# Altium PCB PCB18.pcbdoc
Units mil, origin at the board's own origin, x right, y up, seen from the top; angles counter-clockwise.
Board outline 2150 x 1630 mil, 2 copper layers (Top Layer, Bottom Layer); 39 components, 29 nets, 133 pads, 20 vias.
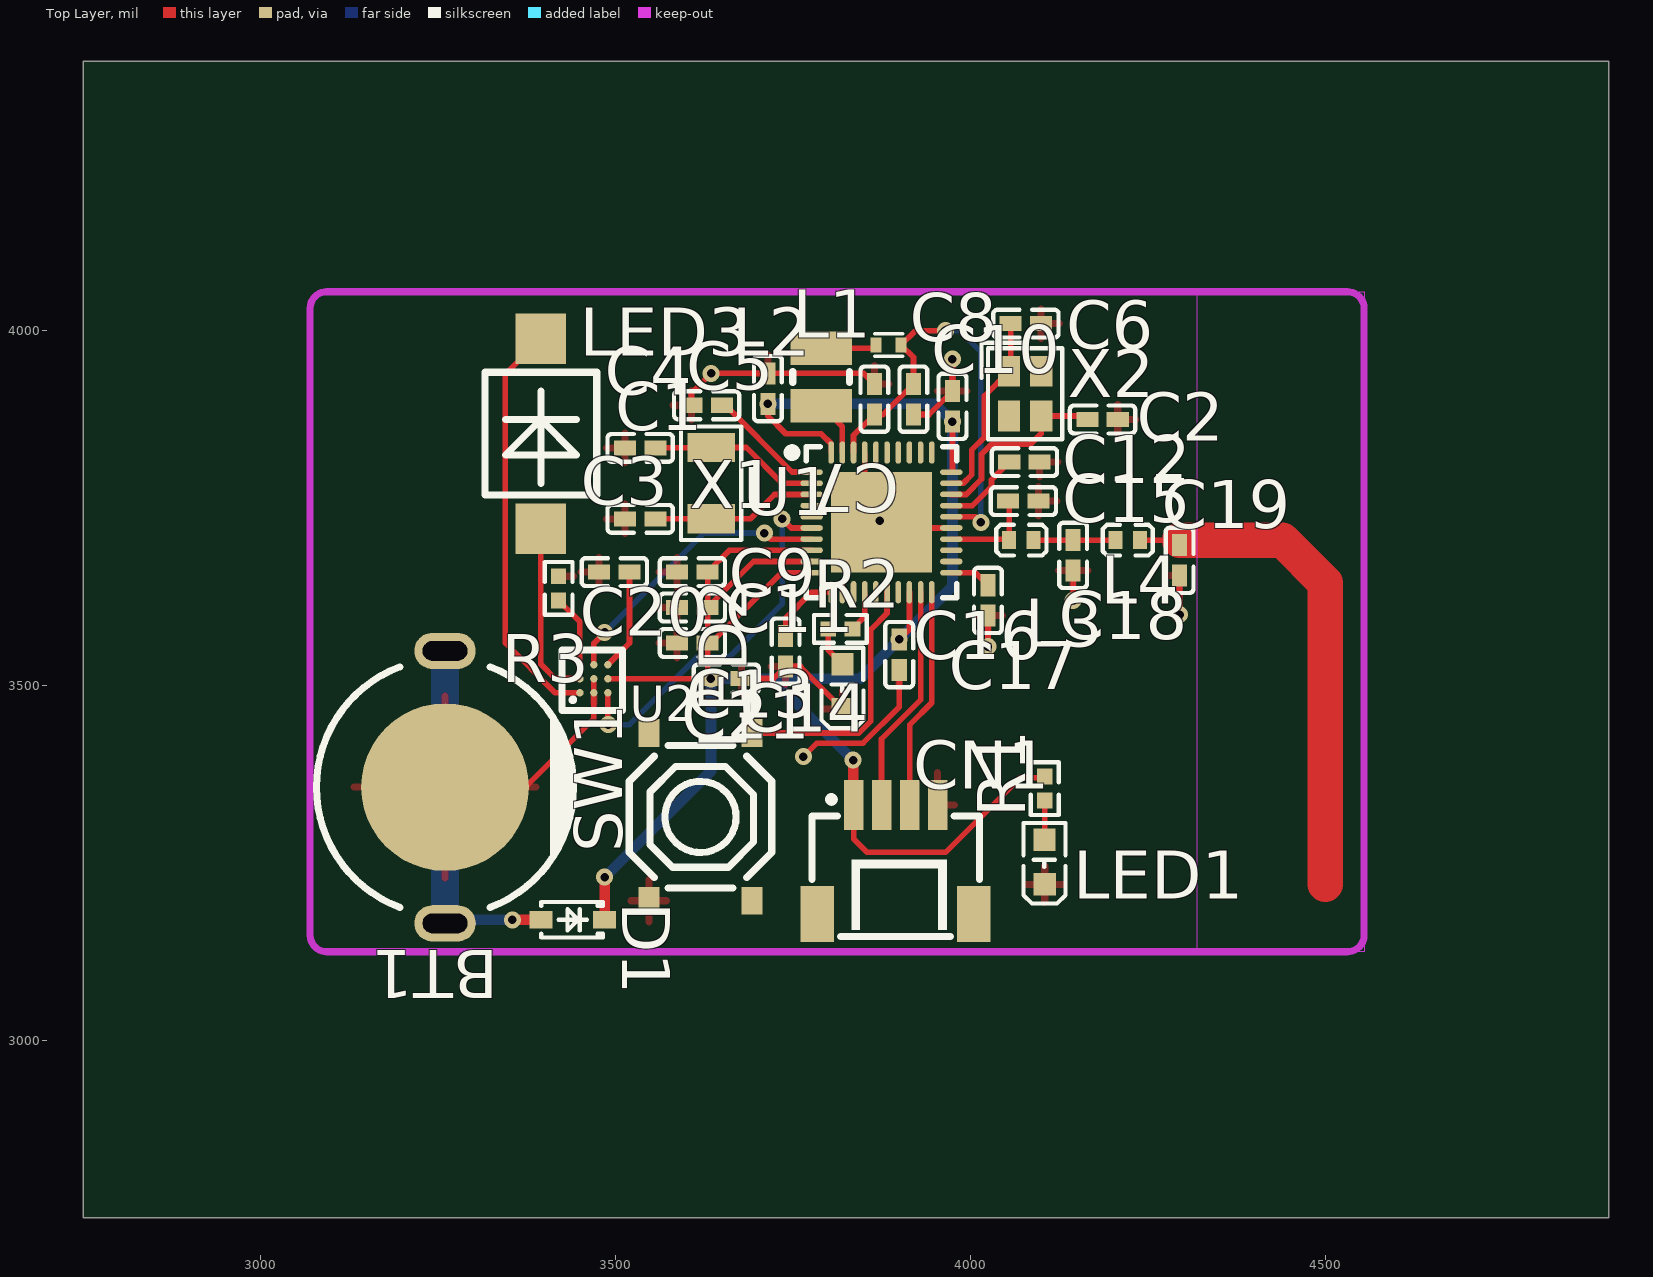
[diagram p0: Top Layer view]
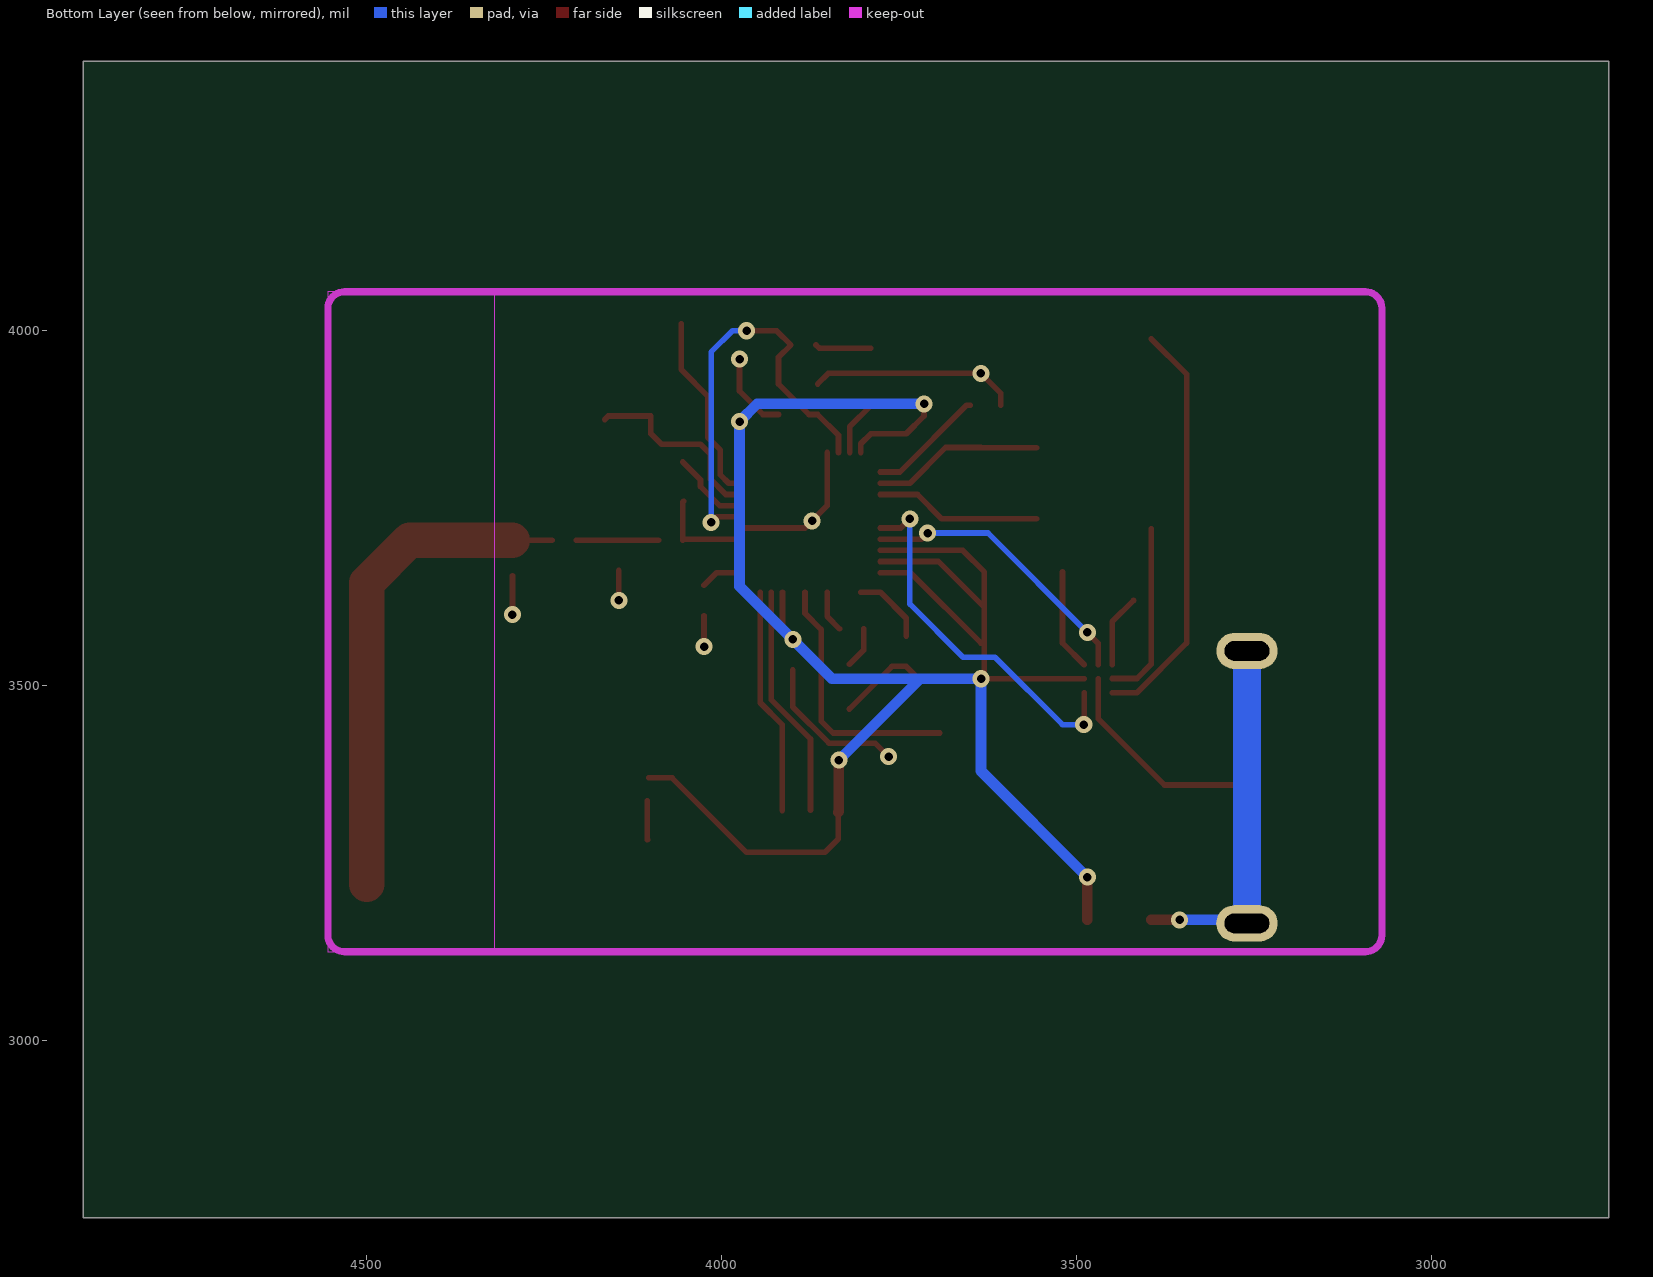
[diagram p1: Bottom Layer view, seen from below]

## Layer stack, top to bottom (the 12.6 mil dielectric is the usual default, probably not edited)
Top Layer: signal copper (thickness not stored)
Dielectric: dielectric 12.6, FR-4, Dk 4.8
Bottom Layer: signal copper (thickness not stored)

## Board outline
4900,2750 2750,2750 2750,4380 4900,4380

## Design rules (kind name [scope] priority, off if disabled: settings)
BoardOutlineClearance safeClearance [All] p0: genericclearance=10 ignorepadtopadclearanceinfootprint=FALSE except(0: Arc-SplitContinuation Track-SplitContinuation SMDPad-SplitContinuation THPad-SplitContinuation Via-SplitContinuation Fill-SplitContinuation Poly-SplitContinuation Region-SplitContinuation Text-SplitContinuation; 6: Track-CutoutEdge SMDPad-CutoutEdge THPad-CutoutEdge Via-CutoutEdge Fill-CutoutEdge Region-CutoutEdge; 11.8: Track-OutlineEdge SMDPad-OutlineEdge THPad-OutlineEdge Via-OutlineEdge Fill-OutlineEdge Region-OutlineEdge Poly-OutlineEdge Text-OutlineEdge)
Clearance safeClearance [(InNet('XL1') OR InNet('XL2') OR InNet('$1N2289') OR InNet('$1N2530') OR InNet('GND') OR InNet('$1N3495') OR InNet('SWDCLK') OR InNet('SWDIO') OR InNet('RESET') OR InNet('$1N1552') OR InNet('VDD_NRF') OR InNet('$1N2985') OR InNet('$1N3242') OR InNet('DEC4') OR InNet('XC1') OR InNet('XC2') OR InNet('DCC') OR InNet('$1N6091') OR InNet('E/CFGCLK') OR InNet('D/CFGDATA') OR InNet('$1N11204') OR InNet('$1N11226') OR InNet('$1N11357') OR InNet('$1N9430') OR InNet('$1N20837') OR InNet('$1N23087') OR InNet('$1N22902') OR InNet('LED') OR InNet('$1N23686'))] p1: gap=7 ignorepadtopadclearanceinfootprint=FALSE except(6: Track-Track Track-SMDPad SMDPad-SMDPad Track-THPad SMDPad-THPad THPad-THPad Track-Via SMDPad-Via THPad-Via Via-Via Track-Fill SMDPad-Fill THPad-Fill Via-Fill Fill-Fill Track-Region SMDPad-Region THPad-Region Via-Region Fill-Region Region-Region Track-Poly SMDPad-Poly THPad-Poly Via-Poly Fill-Poly Region-Poly Poly-Poly Track-Text SMDPad-Text THPad-Text Via-Text Fill-Text Region-Text Poly-Text Text-Text Track-Hole SMDPad-Hole THPad-Hole Via-Hole Fill-Hole Region-Hole Poly-Hole Text-Hole; 11.8: Track-Sheet SMDPad-Sheet THPad-Sheet Via-Sheet Fill-Sheet Region-Sheet Poly-Sheet Text-Sheet Sheet-Hole)
DiffPairsRouting differentialPair [All] p1: maxuncoupledlength=10 minlimit=6 maxlimit=6 mostfreqgap=6 toplayer_minwidth=5 toplayer_prefwidth=10 toplayer_maxwidth=100 bottomlayer_minwidth=5 bottomlayer_prefwidth=10 bottomlayer_maxwidth=100
PasteMaskExpansion pasteMaskExpansion [All] p1: expansion=0
PlaneConnect innerPlane [All] p1: planeconnectstyle=Relief reliefexpansion=20 reliefentries=4 reliefconductorwidth=10 reliefairgap=10
PolygonConnect copperRegion [All] p1: connectstyle=Relief reliefentries=4 reliefconductorwidth=10 polygonreliefangle="90 Angle" airgapwidth=10
RoutingVias viaSize [All] p1: viastyle="Through Hole" holewidth=12.0078 minholewidth=11.811 maxholewidth=236.2204 width=24.0158 minwidth=19.685 maxwidth=393.7008
SolderMaskExpansion solderMaskExpansion [All] p1: useseparateexpansions=TRUE expansion=4 expansionbottom=4
Width trackWidth [All] p1: maxlimit=100 minlimit=5 preferedwidth=8

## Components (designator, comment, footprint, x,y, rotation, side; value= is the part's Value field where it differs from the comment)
BT1 "MY-927-01" BAT-TH_MY-927-01 3259.99,3356.93 r270 top
C1 "GRM1555C1H120JA01D" C0402 3535,3835 r0 top
C2 "GRM1555C1H120JA01D" C0402 4186.46,3875 r0 top
C3 "GRM1555C1H120JA01D" C0402 3535,3735 r0 top
C4 "CL05B104KB54PNC" C0402 3628.54,3895 r180 top
C5 "CL05A105KA5NQNC" C0402 3715,3918.54 r90 top
C6 "GRM1555C1H120JA01D" C0402 4078.54,4010 r0 top
C7 "CC0402KRX7R9BB473" C0402 3865,3903.54 r90 top
C8 "CL05A105KA5NQNC" C0402 3920,3903.54 r270 top
C9 "CL05A475MP5NRNC" C0402 3608.54,3660 r180 top
C10 "CL05B104KB54PNC" C0402 3975,3893.54 r90 top
C11 "CL05A475MP5NRNC" C0402 3608.54,3610 r180 top
C12 "CL05B104KB54PNC" C0402 4076.46,3815 r0 top
C13 "CL05A475MP5NRNC" C0402 3608.54,3560 r180 top
C14 "CL05A475MP5NRNC" C0402 3740,3548.54 r90 top
C15 "GJM1555C1H1R0WB01D" C0402 4075,3760 r0 top
C16 "CL05B104KB54PNC" C0402 3900,3543.54 r90 top
C17 "CC0402KRX7R9BB821" C0402 4025,3620 r270 top
C18 "GJM1555C1H1R2WB01D" C0402 4145,3683.54 r90 top
C19 "GRM1555C1H120JA01D" C0402 4295,3676.46 r90 top
C20 "CL05A105KA5NQNC" C0402 3498.54,3660 r0 top
C21 "CL05B104KB54PNC" C0402 3656.46,3510 r0 top
CN1 "1.0-4PWB" CONN-SMD_4P-P1.00_DEALON_1.0-4PWB 3895,3255 r0 top
D1 "BZT52C3V3S_C19077437" SOD-323_L1.7-W1.3-LS2.6-RD 3440,3170 r180 top
L1 "LQW15AN15NG00D" IND-SMD_L1.0-W0.5-2 3885,3980 r0 top
L2 "FTC252012S100MBCA" IND-SMD_L2.5-W2.0 3790,3935 r90 top
L3 "LQW15AN4N7B00D" IND-SMD_L1.0-W0.6 4072.08,3705 r0 top
L4 "LQW15AN2N2B80D" IND-SMD_L1.0-W0.6 4222.08,3705 r0 top
LED1 "NCD0603G1" LED0603-RD_1 4104.86,3251.47 r90 top
LED2 "NCD0603G1" LED0603-RD_1 3820.14,3498.53 r90 top
LED3 "VBPW34S" SENSOR-SMD_L4.4-W3.9 3395,3855 r90 top
R1 "0402WGF1002TCE" R0402 4105,3355 r90 top
R2 "0402WGF1002TCE" R0402 3817.04,3580 r0 top
R3 "0402WGF1502TCE" R0402 3420,3637.04 r270 top
SW1 "TS-1187A-B-A-B" SW-SMD_4P-L5.1-W5.1-P3.70-LS6.5-TL_H1.5 3620,3315 r90 top
U1 "nRF52833-QDAA-R" QFN-40_L5.0-W5.0-P0.40-TL-EP3.6 3875,3730 r0 top
U2 "TS4231" TS4231 3470,3510 r90 top
X1 "X321532768KGD2SI" OSC-SMD_L3.2-W1.5 3635,3785.2 r90 top
X2 "X201632MOB4SI" CRYSTAL-SMD_4P-L2.0-W1.6-BL-2 4077.36,3911.49 r270 top

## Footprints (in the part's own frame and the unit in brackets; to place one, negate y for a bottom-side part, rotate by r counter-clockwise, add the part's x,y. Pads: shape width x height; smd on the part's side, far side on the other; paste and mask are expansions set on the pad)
BAT-TH_MY-927-01 [mm]
  oval 1.3x2.2 hole 0.7 slot 1.6 at 90 deg: 1(-4.875,0) 1(4.875,0)
  round 6 smd: 2(0,0)
  silkscreen extent -4.31,-4.6 4.31,4.6
C0402 [mm]
  rect 0.79x0.54 smd: 1(-0.545,0) 2(0.545,0)
  silkscreen extent -1.17,-0.5 1.17,0.5
CONN-SMD_4P-P1.00_DEALON_1.0-4PWB [mm]
  rect 0.7x1.8 smd: 1(-1.5,1.95) 2(-0.5,1.95) 3(0.5,1.95) 4(1.5,1.95)
  rect 1.2x2 smd: 5(2.8,-1.95) 6(-2.8,-1.95)
  silkscreen extent -3,-2.75 3,2.25
CRYSTAL-SMD_4P-L2.0-W1.6-BL-2 [mm]
  rect 1.1x0.8 smd: 1(-0.8,-0.575) 2(0.8,-0.575) 3(0.8,0.575) 4(-0.8,0.575)
  silkscreen extent -1.82,-1.56 1.64,1.33
IND-SMD_L1.0-W0.5-2 [mm]
  rect 0.4x0.55 smd: 1(-0.45,0) 2(0.45,0)
  silkscreen extent -0.5,-0.41 0.5,0.41
IND-SMD_L1.0-W0.6 [mm]
  rect 0.5x0.648 smd: 1(-0.434,0) 2(0.434,0)
  silkscreen extent -0.9,-0.55 0.9,0.55
IND-SMD_L2.5-W2.0 [mm]
  rect 1.2x2.2 smd: 1(1.028,0) 2(-1.028,0)
  silkscreen extent -0.2,-1.02 0.2,1.02
LED0603-RD_1 [mm]
  rect 0.8x0.8 smd: 1(-0.799,-0.004) 2(0.799,0.004)
  silkscreen extent -1.49,-0.75 1.39,0.76
OSC-SMD_L3.2-W1.5 [mm]
  rect 1.05x1.7 smd: 1(-1.275,0) 2(1.275,0)
  silkscreen extent -2.03,-1.08 2.03,1.08
QFN-40_L5.0-W5.0-P0.40-TL-EP3.6 [mm]
  oval 0.8x0.2 smd: 1(-2.499,1.8) 2(-2.499,1.4) 3(-2.499,1) 4(-2.499,0.6) 5(-2.499,0.2) 6(-2.499,-0.2) 7(-2.499,-0.6) 8(-2.499,-1) 9(-2.499,-1.4) 10(-2.499,-1.8) 21(2.499,-1.8) 22(2.499,-1.4) 23(2.499,-1) 24(2.499,-0.6) 25(2.499,-0.2) 26(2.499,0.2) 27(2.499,0.6) 28(2.499,1) 29(2.499,1.4) 30(2.499,1.8)
  oval 0.2x0.8 smd: 11(-1.8,-2.499) 12(-1.4,-2.499) 13(-1,-2.499) 14(-0.6,-2.499) 15(-0.2,-2.499) 16(0.2,-2.499) 17(0.6,-2.499) 18(1,-2.499) 19(1.4,-2.499) 20(1.8,-2.499) 31(1.8,2.499) 32(1.4,2.499) 33(1,2.499) 34(0.6,2.499) 35(0.2,2.499) 36(-0.2,2.499) 37(-0.6,2.499) 38(-1,2.499) 39(-1.4,2.499) 40(-1.8,2.499)
  rect 3.6x3.6 smd: 41(0,0)
  silkscreen extent -3.35,-2.7 2.7,2.7
R0402 [mm]
  rect 0.566x0.54 smd: 1(-0.433,0) 2(0.433,0)
  silkscreen extent -0.94,-0.5 0.94,0.5
SENSOR-SMD_L4.4-W3.9 [mm]
  rect 1.8x1.8 smd: 1(-3.4,0) 2(3.4,0)
  silkscreen extent -2.2,-2 2.2,2
SOD-323_L1.7-W1.3-LS2.6-RD [mm]
  rect 0.83x0.63 smd: 1(-1.14,0) 2(1.14,0)
  silkscreen extent -1.08,-0.64 1.13,0.64
SW-SMD_4P-L5.1-W5.1-P3.70-LS6.5-TL_H1.5 [mm]
  rect 1x0.75 smd: 1(-3,1.85) 2(3,1.85) 3(-3,-1.85) 4(3,-1.85)
  silkscreen extent -2.55,-2.55 2.55,2.55
TS4231 [mil]
  round 10.31 smd: 1(-20,20) 2(-0.32,20) 3(19.37,20) 4(-20,0.32) 5(-0.32,0.32) 6(19.37,0.32) 7(-20,-19.37) 8(-0.32,-19.37) 9(19.37,-19.37)
  silkscreen extent -45,-40 40,45

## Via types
v1: diameter 24.02, hole 12.01, Top Layer to Bottom Layer, 20 vias

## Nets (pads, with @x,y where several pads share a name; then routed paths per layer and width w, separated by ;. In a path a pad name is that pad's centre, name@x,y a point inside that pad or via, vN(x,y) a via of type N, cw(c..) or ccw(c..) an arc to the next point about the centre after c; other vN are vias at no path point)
$1N1552: C14.2 U1.11 | length 104.3
  Top Layer w8: C14.2 3740,3595 3776.6,3631.6 U1.11
$1N2289: C17.1 U1.21 | length 58.9
  Top Layer w8: U1.21 4007.33,3659.13 C17.1
$1N2530: C15.1 L3.1 U1.24 | length 137.8
  Top Layer w8: U1.24 4053.62,3706.38 L3.1 4055,3758.54 C15.1
$1N2985: C18.2 L3.2 L4.1 | length 115.8
  Top Layer w8: L3.2 C18.2 L4.1
$1N3242: C19.2 L4.2 | length 710.7
  Top Layer w8: L4.2 C19.2@4295,3705
  Top Layer w50: C19.2@4295,3705 4440,3705 4500,3645 4500,3220
$1N3495: C12.1 U1.27 | length 112.6
  Top Layer w8: U1.27 4003.12,3753.62 4030,3780.5 4030,3790 C12.1
$1N6091: L1.1 L2.1 | length 79.2
  Top Layer w8: L2.1 3862.76,3975.48 L1.1
$1N9430: C20.2 U2.9 | length 143.3
  Top Layer w8: U2.9 3520,3560 C20.2
$1N11204: LED3.2 U2.1 | length 583.6
  Top Layer w8: LED3.2 3345,3938.86 3345,3560 3415,3490 U2.1
$1N11226: LED3.1 U2.2 | length 254.6
  Top Layer w8: LED3.1 3395,3530 3415,3510 3449.68,3510 U2.2
$1N11357: R3.2 U2.3 | length 103.1
  Top Layer w8: R3.2 3450,3590 U2.3
$1N20837: BT1.1 D1.2 | length 514.7
  Top Layer w15: v1(3355,3170) D1.2
  Bottom Layer w15: BT1.1@3260.01,3168.07 3261.95,3170 v1(3355,3170)
  Bottom Layer w40: BT1.1@3260.01,3168.07 BT1.1@3260.01,3546.89
$1N22902: LED2.2 R2.1 | length 58.3
  Top Layer w8: R2.1 3800,3550 LED2.2
$1N23087: C4.1 U1.1 | length 165.6
  Top Layer w8: C4.1 3655,3895 3749.13,3800.87 U1.1
$1N23686: LED1.2 R1.1 | length 55.1
  Top Layer w8: LED1.2 4105,3283.23 R1.1
D/CFGDATA: U1.7 U2.6 | length 405.1
  Top Layer w8: U2.6 3469.68,3559.68 v1(3485,3575) ; v1(3710,3715) 3718.62,3706.38 U1.7
  Bottom Layer w8: v1(3485,3575) 3625,3715 v1(3710,3715)
DCC: L2.2 U1.39 | length 78.5
  Top Layer w8: L2.2 3819.88,3864.64 U1.39
DEC4: C7.1 C8.1 L1.2 U1.26 U1.38 | length 618.6
  Top Layer w8: U1.38 3835.63,3852.71 C7.1 3877.08,3882.08 C8.1 3920,3962.72 L1.2 3922.72,4000 v1(3965,4000) ; U1.26 4007.13,3737.87 v1(4015,3730)
  Bottom Layer w8: v1(3965,4000) 3985,4000 4015,3970 v1(4015,3730)
E/CFGCLK: U1.6 U2.7 | length 527.6
  Top Layer w8: U2.7 3489.37,3445.63 v1(3490,3445) ; v1(3735,3735) 3747.87,3722.13 U1.6
  Bottom Layer w8: v1(3490,3445) 3520,3445 3615,3540 3660,3540 3735,3615 v1(3735,3735)
GND: BT1.2 C1.1 C2.2 C3.1 C4.2 C5.2 C6.2 C7.2 C8.2 C9.2 C10.2 C11.2 C12.2 C13.2 C14.1 C15.2 C16.1 C17.2 C18.1 C19.1 C20.1 C21.2 CN1.4 LED1.1 LED2.1 R3.1 SW1.1 U1.25 U1.37 U1.41 U2.4 U2.5 | length 1451.9
  Top Layer w8: BT1.2@3259.99,3360 3376.22,3360 3469.68,3453.46 U2.4 U2.5 ; C4.2 3607.08,3912.08 v1(3635,3940) C5.2 3850,3940 C7.2 ; C21.2 3722.92,3510 C14.1 3760.25,3527.08 LED2.1 ; v1(3765,3400) 3784,3419 3849,3419 3900,3470 C16.1 ; U1.37 3851.38,3753.62 v1(3872.74,3732.26) 3882.87,3722.13 U1.25 ; C8.2 3942.08,3882.08 C10.2 v1(3975,3960) ; v1(4025,3555) C17.2 ; v1(4145,3620) C18.1 ; v1(4295,3600) C19.1
LED: R2.2 U1.14 | length 58.8
  Top Layer w8: R2.2 3851.38,3597.3 U1.14
RESET: SW1.4 U1.16 | length 365.2
  Top Layer w8: SW1.4 3843.11,3433.11 3860,3450 3860,3579.01 3882.87,3601.88 U1.16
SWDCLK: CN1.3 U1.20 | length 320.4
  Top Layer w8: CN1.3@3915,3324 3915,3445 3945.87,3475.87 U1.20
SWDIO: CN1.2 U1.19 | length 329.8
  Top Layer w8: CN1.2@3875,3324.8 3875,3424.8 3930.12,3479.92 3930.12,3580.12 ; 3930,3580 3930.12,3580.12 ; U1.19 3930.12,3580.12
VDD_NRF: C5.1 C9.1 C10.1 C11.1 C13.1 C16.2 C21.1 CN1.1 D1.1 R1.2 U1.8 U1.9 U1.10 U1.18 U1.30 U1.40 U2.8 | length 2988.1
  Top Layer w8: U2.8 v1(3634.68,3509.68) ; C21.1 v1(3634.68,3509.68) ; v1(3715,3897.08) 3715,3880 3740,3855 3790,3855 3804.13,3840.87 U1.40 ; U1.10 3734.13,3659.13 3635,3560 C13.1 ; U1.9 3694.88,3674.88 C11.1 ; U1.8 3660.63,3690.63 C9.1 C11.1 ; CN1.1@3835.94,3321.77 3835.94,3284.06 3855,3265 3965,3265 4070,3370 R1.2@4102.96,3370 ; v1(3900,3565) 3914.37,3579.37 U1.18 ; U1.30 3975,3802.47 v1(3975,3872.08) ; C13.1 C11.1 ; C13.1 3630,3514.37 v1(3634.68,3509.68)
  Top Layer w15: D1.1 3485,3170.12 v1(3485,3230) ; v1(3835,3395) 3835,3322.71 CN1.1@3835.94,3321.77
  Bottom Layer w15: v1(3485,3230) 3634.68,3379.68 v1(3634.68,3509.68) 3720.32,3509.68 ; v1(3715,3897.08) 3950,3897.08 v1(3975,3872.08) 3975,3640 v1(3900,3565) 3844.68,3509.68 3720.32,3509.68 ; v1(3835,3395) 3720.32,3509.68
XC1: C2.1 U1.28 X2.3 | length 274.6
  Top Layer w8: U1.28 3994.37,3769.37 4016,3791 4016,3826 4030,3840 4085,3840 4100,3855 X2.3 4160,3880 C2.1
XC2: C6.1 U1.29 X2.1 | length 269.3
  Top Layer w8: U1.29 3990.12,3785.12 4002,3797 4002,3832 4020,3850 4020,3908.27 X2.1 4057.08,3945.35 C6.1
XL1: C1.2 U1.2 X1.2 | length 241.1
  Top Layer w8: C1.2 3634.6,3835 X1.2 3684.6,3835.4 3734.88,3785.12 U1.2
XL2: C3.2 U1.3 X1.1 | length 234.4
  Top Layer w8: C3.2 X1.1 3690,3735 3724.37,3769.37 U1.3
pads on no net: CN1.5 CN1.6 SW1.2 SW1.3 U1.4 U1.5 U1.12 U1.13 U1.15 U1.17 U1.22 U1.23 U1.31 U1.32 U1.33 U1.34 U1.35 U1.36 X2.2 X2.4

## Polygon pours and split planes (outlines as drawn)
GND on Top Layer (solid, remove dead copper, pour order 0): 3000,4105 4650,4105 4650,3000 3000,3000
GND on Bottom Layer (solid, remove dead copper, pour order 2): 3025,4130 4615,4130 4615,3035 3025,3035

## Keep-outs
Board Outline Layer:
  region: 4320,4055 4555,4055 4555,3125 4320,3125
  lines w10: 3070,3148.25 ccw(c3093.25,3148.25) 3093.25,3125 4531.75,3125 ccw(c4531.75,3148.25) 4555,3148.25 4555,4031.75 ccw(c4531.75,4031.75) 4531.75,4055 3093.25,4055 ccw(c3093.25,4031.75) 3070,4031.75 3070,3148.25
